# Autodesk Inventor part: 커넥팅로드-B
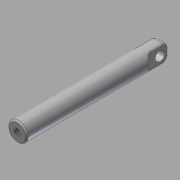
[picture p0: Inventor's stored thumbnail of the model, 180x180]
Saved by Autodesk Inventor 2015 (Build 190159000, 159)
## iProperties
Created: 2018-01
Part Number: 커넥팅로드-B
Material: 강철, 연강
Document SubType Name: Modeling
Designer: mduedu
Density: 7.86 g/cm^3
Appearance: 강철
Mass: 14.5817 g
Surface Area: 12.9188 cm^2
Volume: 1.85518 cm^3
Author: mduedu
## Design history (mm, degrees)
sketch "스케치1"
  geometry: C1 r 3.5 at (0, 0); 1 further point
  constraints: 1 centre point, 1 coincident
  dimensions: "d0" = 7 diameter of C1
extrude "돌출1" new body sketch "스케치1" distance "d1" = 53; taper "d2" = 0 deg
node "작업 평면1"
sketch "스케치2"
  geometry: L1 (-3.5, 0)-(3.5, 0) reference; L2 (4, 4)-(4, 0); L3 (4, 0)-(-4, 0); L4 (-4, 0)-(-4, 4); A1 r 4 centre (0, 4) between (4, 4) and (-4, 4); 2 further points
  constraints: 6 end point, 2 perpendicular, 2 point on circle, 2 tangent, 1 centre point, 1 collinear, 1 midpoint, 1 vertical, 1 vertical alignment
  dimensions: "d4" = 8 diameter of A1; "d5" = 4 distance from line of A1.centre L1
extrude "돌출2" cut sketch "스케치2" stored distance "d6" = 53; taper "d7" = 0 deg
fillet "모깎기1" dims "d8" = 2
fillet "모깎기2" dims "d9" = 0.5
fillet "모깎기3" dims "d10" = 0.5
sketch "스케치3"
  geometry: C1 r 1.75 at (0, 3); 1 further point
  constraints: 1 centre point, 1 vertical alignment
  dimensions: "d11" = 3.5 diameter of C1; "d12" = 3 distance of point (0, 0) C1.centre
extrude "돌출3" cut sketch "스케치3" stored distance "d13" = 53; taper "d14" = 0 deg
chamfer "모따기1" distance "d15" = 0.5; stored, may be unused: second distance "d16" = 2, angle "d17" = 45 deg
sketch "스케치4"
  geometry: 1 further point
hole "구멍1" sketch "스케치4" at (0, 0) diameter "d18" = 2.459; stored, may be unused: countersink angle "d22" = 90 deg, drill point angle "d24" = 120 deg; dims "d19" = 6.9, "d20" = 4, "d21" = 2, "d23" = 8.4
node "솔리드1"
mirror "대칭1"
other parameters: "d3" = 2
